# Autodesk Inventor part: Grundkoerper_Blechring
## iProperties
Company: Florian Eichinger GmbH
Created: 2008-02
Part Number: Grundkoerper_Blechring
Material: S235JRG2
Document SubType Name: Blech
Designer: resitib
Density: 7.86 g/cm^3
D_Silo_IK: 1000,000 mm
Höhe_Blechring: 250,000 mm
Blechdicke: 2,500 mm
d6: 100,000 mm
d2: 0,00 grd
d7: 50,000 mm
Winkel_Aufschnitt: 0,10 grd
d10: 50,000 mm
d11: 50,000 mm
Author: resitib
Comments: Vorlage Bauteil Eichinger.ipt
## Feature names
1. Umdrehung1 [Revolution]
